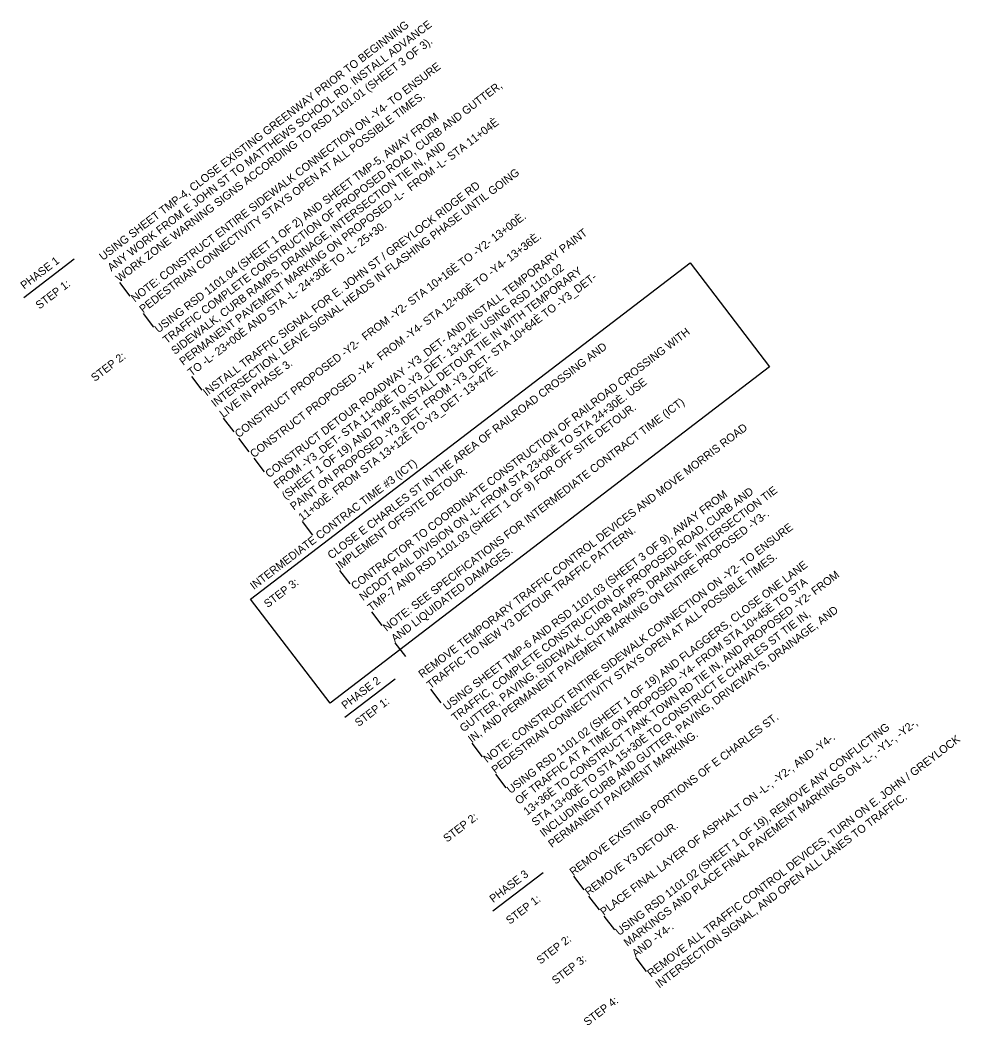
# Model space of a CAD drawing. Extents: x -606 to 2396, y -305 to 3662.
# Drawn here: x -453 to 370, y 2783 to 3662 of the extents above; entities that cross this region are included whole.
import ezdxf

# ---------------------------------------------------------------- set-up
doc = ezdxf.new("R2010")
doc.units = 0
doc.layers.add('Scratch_Level_4', color=7, linetype='Continuous')
doc.layers.add('Text', color=7, linetype='Continuous')

msp = doc.modelspace()

# ---------------------------------------------------------------- linework, layer by layer
at = {"layer": 'Scratch_Level_4'}
for p, q in [((-365.94, 3432.74), (-356.83, 3420.83)), ((-345.35, 3405.81), (-336.24, 3393.9)), ((-303.07, 3350.52), (-293.96, 3338.61)), ((-275.25, 3314.14), (-266.14, 3302.23)), ((-261.89, 3296.67), (-252.78, 3284.75)), ((-248.53, 3279.19), (-239.42, 3267.27)), ((-206.25, 3223.9), (-197.14, 3211.99)), ((-173.58, 3181.17), (-164.46, 3169.26)), ((-145.76, 3144.79), (-136.64, 3132.87)), ((-125.16, 3117.86), (-116.05, 3105.94)), ((-94.09, 3077.23), (-84.98, 3065.31)), ((-57.95, 3029.96), (-48.84, 3018.05)), ((-37.36, 3003.03), (-28.25, 2991.12)), ((30.86, 2913.82), (39.97, 2901.91)), ((44.22, 2896.35), (53.33, 2884.43)), ((57.58, 2878.87), (66.69, 2866.96)), ((85.4, 2842.49), (94.51, 2830.57))]:
    msp.add_line(p, q, dxfattribs=at)
at = {"layer": 'Text'}
for p, q in [((-449.6, 3419.85), (-405.72, 3453.41)), ((-168.9, 3052.76), (-125.02, 3086.32)), ((-39.54, 2883.59), (4.35, 2917.14))]:
    msp.add_line(p, q, dxfattribs=at)
msp.add_lwpolyline([(-251.44, 3156), (132.92, 3449.9), (202.47, 3358.95), (-181.89, 3065.04)], close=True, dxfattribs=at)

# ---------------------------------------------------------------- texts
for s, p in [('USING SHEET TMP-4, CLOSE EXISTING GREENWAY PRIOR TO BEGINNING ', (-380.4, 3451.65)), ('ANY WORK FROM E JOHN ST TO MATTHEWS SCHOOL RD. INSTALL ADVANCE ', (-373.17, 3442.19)), ('WORK ZONE WARNING SIGNS ACCORDING TO RSD 1101.01 (SHEET 3 OF 3).', (-365.94, 3432.74)), ('NOTE: CONSTRUCT ENTIRE SIDEWALK CONNECTION ON -Y4- TO ENSURE ', (-352.58, 3415.27)), ('TRAFFIC COMPLETE CONSTRUCTION OF PROPOSED ROAD, CURB AND GUTTER, ', (-324.76, 3378.88)), ('PEDESTRIAN CONNECTIVITY STAYS OPEN AT ALL POSSIBLE TIMES.', (-345.35, 3405.81)), ('USING RSD 1101.04 (SHEET 1 OF 2) AND SHEET TMP-5, AWAY FROM ', (-331.99, 3388.34)), ('PERMANENT PAVEMENT MARKING ON PROPOSED -L-  FROM -L- STA 11+04È ', (-310.3, 3359.98)), ('SIDEWALK, CURB RAMPS, DRAINAGE, INTERSECTION TIE IN, AND ', (-317.53, 3369.43)), ('INTERSECTION. LEAVE SIGNAL HEADS IN FLASHING PHASE UNTIL GOING ', (-282.48, 3323.59)), ('INSTALL TRAFFIC SIGNAL FOR E. JOHN ST / GREYLOCK RIDGE RD ', (-289.71, 3333.05)), ('CONSTRUCT PROPOSED -Y2-  FROM -Y2- STA 10+16È TO -Y2- 13+00È.', (-261.89, 3296.67)), ('TO -L- 23+00È AND STA -L- 24+30È TO -L- 25+30.', (-303.07, 3350.52)), ('CONSTRUCT PROPOSED -Y4-  FROM -Y4- STA 12+00È TO -Y4- 13+36È.', (-248.53, 3279.19)), ('CONSTRUCT DETOUR ROADWAY -Y3_DET- AND INSTALL TEMPORARY PAINT ', (-235.16, 3261.71)), ('PHASE 1', (-449.27, 3426.48)), ('FROM -Y3_DET- STA 11+00È TO -Y3_DET- 13+12È. USING RSD 1101.02 ', (-227.94, 3252.26)), ('(SHEET 1 OF 19) AND TMP-5 INSTALL DETOUR TIE IN WITH TEMPORARY ', (-220.71, 3242.81)), ('PAINT ON PROPOSED -Y3_DET- FROM -Y3_DET- STA 10+64È TO -Y3_DET- ', (-213.48, 3233.35)), ('STEP 1:', (-436.01, 3409.13)), ('CONTRACTOR TO COORDINATE CONSTRUCTION OF RAILROAD CROSSING WITH ', (-160.21, 3163.69)), ('CLOSE E CHARLES ST IN THE AREA OF RAILROAD CROSSING AND ', (-180.8, 3190.62)), ('STEP 2:', (-387.59, 3345.82)), ('LIVE IN PHASE 3.', (-275.25, 3314.14)), ('11+00È. FROM STA 13+12È TO-Y3_DET- 13+47È.', (-206.25, 3223.9)), ('NCDOT RAIL DIVISION ON -L- FROM STA 23+00È TO STA 24+30È. USE ', (-152.98, 3154.24)), ('TMP-7 AND RSD 1101.03 (SHEET 1 OF 9) FOR OFF SITE DETOUR.', (-145.76, 3144.79)), ('NOTE: SEE SPECIFICATIONS FOR INTERMEDIATE CONTRACT TIME (ICT) ', (-132.39, 3127.31)), ('REMOVE TEMPORARY TRAFFIC CONTROL DEVICES AND MOVE MORRIS ROAD ', (-101.32, 3086.68)), ('INTERMEDIATE CONTRAC TIME #3 (ICT)', (-248.49, 3163.9)), ('IMPLEMENT OFFSITE DETOUR.', (-173.58, 3181.17)), ('GUTTER, PAVING, SIDEWALK, CURB RAMPS, DRAINAGE, INTERSECTION TIE ', (-65.18, 3039.41)), ('USING SHEET TMP-6 AND RSD 1101.03 (SHEET 3 OF 9), AWAY FROM ', (-79.64, 3058.32)), ('TRAFFIC, COMPLETE CONSTRUCTION OF PROPOSED ROAD, CURB AND ', (-72.41, 3048.87)), ('IN, AND PERMANENT PAVEMENT MARKING ON ENTIRE PROPOSED -Y3-.', (-57.95, 3029.96)), ('TRAFFIC TO NEW Y3 DETOUR TRAFFIC PATTERN.', (-94.09, 3077.23)), ('NOTE: CONSTRUCT ENTIRE SIDEWALK CONNECTION ON -Y2- TO ENSURE ', (-44.59, 3012.49)), ('AND LIQUIDATED DAMAGES.', (-125.16, 3117.86)), ('PEDESTRIAN CONNECTIVITY STAYS OPEN AT ALL POSSIBLE TIMES.', (-37.36, 3003.03)), ('USING RSD 1101.02 (SHEET 1 OF 19) AND FLAGGERS, CLOSE ONE LANE ', (-24, 2985.56)), ('13+36È TO CONSTRUCT TANK TOWN RD TIE IN, AND PROPOSED -Y2- FROM ', (-9.54, 2966.65)), ('STEP 3:', (-236.41, 3148.1)), ('OF TRAFFIC AT A TIME ON PROPOSED -Y4- FROM STA 10+45È TO STA ', (-16.77, 2976.1)), ('INCLUDING CURB AND GUTTER, PAVING, DRIVEWAYS, DRAINAGE, AND ', (4.92, 2947.74)), ('STA 13+00È TO STA 15+30È TO CONSTRUCT E CHARLES ST TIE IN, ', (-2.31, 2957.2)), ('PHASE 2', (-168.57, 3059.38)), ('STEP 1:', (-156.93, 3044.16)), ('REMOVE EXISTING PORTIONS OF E CHARLES ST.', (30.86, 2913.82)), ('USING RSD 1101.02 (SHEET 1 OF 19), REMOVE ANY CONFLICTING ', (70.95, 2861.4)), ('MARKINGS AND PLACE FINAL PAVEMENT MARKINGS ON -L-, -Y1-, -Y2-, ', (78.17, 2851.94)), ('PERMANENT PAVEMENT MARKING.', (12.15, 2938.29)), ('PLACE FINAL LAYER OF ASPHALT ON -L-, -Y2-, AND -Y4-.', (57.58, 2878.87)), ('REMOVE ALL TRAFFIC CONTROL DEVICES, TURN ON E. JOHN / GREYLOCK ', (98.77, 2825.01)), ('INTERSECTION SIGNAL, AND OPEN ALL LANES TO TRAFFIC.', (105.99, 2815.56)), ('STEP 2:', (-79.6, 2943.04)), ('REMOVE Y3 DETOUR.', (44.22, 2896.35)), ('PHASE 3', (-39.21, 2890.21)), ('STEP 1:', (-24.75, 2871.3)), ('AND -Y4-.', (85.4, 2842.49)), ('STEP 2:', (1.98, 2836.35)), ('STEP 3:', (15.34, 2818.88)), ('STEP 4:', (43.16, 2782.49))]:
    msp.add_text(s, height=7, rotation=37.40396, dxfattribs=at).set_placement(p)

doc.saveas('drawing.dxf')
